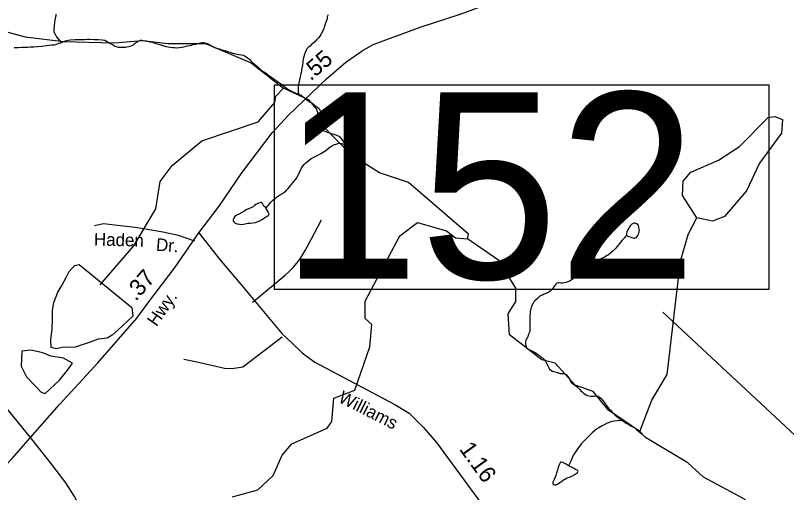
# Model space of a CAD drawing. Extents: x 2126262 to 2293712, y 749403 to 919119.
# Drawn here: x 2226868 to 2232664, y 782434 to 786018 of the extents above; entities that cross this region are included whole.
import ezdxf

# ---------------------------------------------------------------- set-up
doc = ezdxf.new("R2010")
doc.units = 0
for name, color, linetype in [('Exist Hydrographic Creek Single Shore', 7, 'Continuous'), ('Exist Hydrographic Misc Water Feature', 7, 'Continuous'), ('Exist Hydrographic Pond Over 1500 Sq Ft', 7, 'Continuous'), ('Exist Hydrographic Pond Under 1500 Sq Ft', 7, 'Continuous'), ('Exist Hydrographic Stream', 7, 'Continuous'), ('Exist Road Non-System Type 51', 7, 'Continuous'), ('Exist Road Non-System Type 51 Label', 7, 'Continuous'), ('Exist Road Secondary Mileage Hundredths English Label', 7, 'Continuous'), ('Exist Road Secondary Structure Standard Bridge Number Label', 7, 'Continuous'), ('Exist Road Secondary Type 51 Attributed', 7, 'Continuous'), ('Exist Road Secondary Type 51 Label', 7, 'Continuous')]:
    doc.layers.add(name, color=color, linetype=linetype)

msp = doc.modelspace()

# ---------------------------------------------------------------- linework, layer by layer
at = {"layer": 'Exist Hydrographic Creek Single Shore'}
for points in [[(2226705.1, 785919), (2226942.7, 785856.7), (2227230.2, 785821.6), (2227614.1, 785811.8), (2227822.2, 785830.4), (2228013.1, 785806.7), (2228297.1, 785807.5), (2228639.2, 785662.6), (2228883.2, 785470.7)], [(2230266.3, 784340.1), (2230274.3, 784375.9), (2229821.3, 784762.5), (2229604.1, 784835.9), (2229395.2, 784968.1), (2229160.2, 785205.8), (2229134.2, 785314.6), (2229075.1, 785381.5), (2228883.2, 785470.7)], [(2231561.2, 782893), (2231326.2, 783052.1), (2231209.3, 783192.2), (2231075.2, 783240.9), (2230924.3, 783404.8), (2230823.2, 783429.8), (2230580.2, 783618.5), (2230571.2, 783776.1), (2230628.2, 783870.1), (2230628.2, 783968.5), (2230501.3, 784177.8), (2230266.3, 784340.1)], [(2233735.1, 781992.2), (2233626.3, 782037.1), (2233349.7, 782118.2), (2233278.9, 782118.2), (2233213.7, 782138.7), (2233083.3, 782187.2), (2232927.7, 782184.1), (2232856, 782207.7), (2232796.4, 782211.4), (2232574.1, 782235.9), (2232499.3, 782244), (2232348.2, 782384.8), (2232038.1, 782548.7), (2231921.2, 782656.1), (2231603.2, 782846.3), (2231561.2, 782893)]]:
    msp.add_lwpolyline(points, dxfattribs=at)
at = {"layer": 'Exist Hydrographic Misc Water Feature'}
msp.add_line((2228976.8, 785433.8), (2228995.1, 785428.2), dxfattribs=at)
for points in [[(2229218.2, 786023.7), (2229212, 786007.5), (2229210.4, 785991.6), (2229196.9, 785951.5), (2229188.9, 785929.5), (2229184.8, 785919.2), (2229173.1, 785893.4), (2229163.4, 785875.4), (2229155.4, 785863.2), (2229145.8, 785848.8), (2229133.5, 785836.8), (2229119.8, 785822.7), (2229105.8, 785810.6), (2229089.8, 785796.4), (2229082.2, 785788.6), (2229068.3, 785776.6), (2229058, 785766.3), (2229054.4, 785756.4), (2229046.6, 785740.5), (2229038.6, 785720.2), (2229034.9, 785708.2), (2229031, 785690.1), (2229028.9, 785678.2), (2229027.1, 785662.2), (2229024.8, 785646), (2229021.3, 785622.1), (2229019.3, 785610.3), (2229017.6, 785598), (2229013.3, 785582), (2229009.9, 785565.9), (2229007.8, 785558.1), (2229002.1, 785533.8), (2228998.4, 785512), (2228996.5, 785498.1), (2228994.3, 785479.8), (2228992.6, 785457.7), (2228992.8, 785446), (2228995.1, 785428.2)], [(2227214.8, 785815.4), (2227230.2, 785821.6), (2227244.4, 785827.5), (2227264.2, 785831.8), (2227282.3, 785836), (2227316.3, 785838.2), (2227334.6, 785838.3), (2227352, 785838.5), (2227368.6, 785838.4), (2227388.3, 785838.7), (2227406.6, 785838.8), (2227428.3, 785839.1), (2227460.3, 785837.1), (2227492.1, 785837.6), (2227520.4, 785835.8), (2227540, 785832), (2227552.3, 785826.1), (2227562.4, 785820.1), (2227570.2, 785814), (2227580.2, 785808.1), (2227592.5, 785802.2), (2227602.6, 785796.6), (2227616.5, 785788.4), (2227632.5, 785782.7), (2227642.6, 785780.8), (2227658.8, 785778.8), (2227668.4, 785778.9), (2227684.6, 785778.9), (2227694.4, 785779.1), (2227706.5, 785783.3), (2227720.5, 785785.3), (2227730.7, 785787.4), (2227742.4, 785791.7), (2227752.3, 785797.5), (2227760.3, 785801.6), (2227770.5, 785811.8), (2227778.3, 785817.9), (2227791.8, 785826), (2227808.2, 785832.1), (2227818.1, 785832.2), (2227839.8, 785828.5), (2227854, 785826.4), (2227861.8, 785824.4), (2227879.8, 785820.8), (2227898.3, 785816.8), (2227916.5, 785810.8), (2227932.5, 785805.2), (2227952.4, 785799.4), (2227974.3, 785793.6), (2228000.2, 785785.6), (2228016.6, 785781.9), (2228032.4, 785780), (2228050.8, 785778), (2228066.6, 785776.4), (2228080.4, 785774.3), (2228102.5, 785776.7), (2228118.5, 785778.8), (2228134.5, 785782.8), (2228152.1, 785787.1), (2228164.2, 785790.9), (2228192.1, 785795.2), (2228200.5, 785799.2), (2228226.4, 785803.5), (2228238, 785807.8), (2228248.1, 785809.9), (2228260, 785811.8), (2228272.1, 785816), (2228281.9, 785814.1), (2228292, 785812.2), (2228302.2, 785810.2), (2228316.2, 785804.5), (2228322.3, 785800.3), (2228334.4, 785794.4), (2228342.2, 785790.4), (2228364.6, 785778.5), (2228380.5, 785772.9), (2228400.4, 785767), (2228418.5, 785761), (2228430.6, 785757.2), (2228448.8, 785751.2), (2228470.8, 785745.4), (2228482.9, 785741.6), (2228500.5, 785735.6), (2228514.9, 785731.9), (2228532.5, 785728), (2228548.9, 785724.3), (2228566.7, 785722.4), (2228581.1, 785718.7), (2228590.5, 785714.4), (2228609, 785702.7), (2228627, 785689), (2228635, 785680.9), (2228644.9, 785670.9), (2228651.2, 785665.1), (2228677.3, 785641.2), (2228701.7, 785619.3), (2228717.7, 785605.5), (2228735.7, 785593.9), (2228751.9, 785583.7), (2228764, 785572.2)], [(2226858.9, 785776.2), (2226871, 785776.4), (2226888.8, 785776.6), (2226916.7, 785778.8), (2226940.9, 785780.9), (2226958.7, 785781), (2226980.9, 785783.4), (2227006.7, 785783.5), (2227034.8, 785785.8), (2227064.9, 785788.1), (2227100.8, 785792.4), (2227120.9, 785794.6), (2227140.6, 785796.5), (2227156.8, 785798.6), (2227172.4, 785801.1), (2227194.5, 785809.1), (2227206.6, 785812.9), (2227214.8, 785815.4)], [(2228764, 785572.2), (2228792.1, 785554.1), (2228812, 785538.5), (2228834.3, 785524.6), (2228846.2, 785516.8), (2228868.2, 785500.9), (2228888.5, 785485.2), (2228902.6, 785475.4), (2228916.6, 785465.1), (2228932.8, 785455.4), (2228952.9, 785445.5), (2228970.7, 785437.9), (2228976.8, 785433.8)], [(2227504.2, 783993.4), (2227759.1, 784286.7), (2227924.1, 784565.4), (2227955.1, 784771.4), (2228046.1, 784890.9), (2228269.3, 785076.5), (2228693.1, 785218.7), (2228817.2, 785363.8), (2228825.2, 785412.8), (2228883.2, 785470.7)], [(2228995.1, 785428.2), (2229003.3, 785424.1), (2229017.2, 785416.3), (2229026.9, 785410.4), (2229037.1, 785402.3), (2229051.3, 785390.5), (2229065.4, 785378.6), (2229079.4, 785368.8), (2229093.5, 785361), (2229105.8, 785353), (2229115.9, 785345), (2229129.6, 785335.2), (2229137.8, 785329.1), (2229149.9, 785319.2), (2229155.9, 785307.3), (2229162, 785295.4), (2229164.1, 785279.3), (2229163.8, 785271.2), (2229164.3, 785257.4), (2229164.1, 785241.6), (2229164.7, 785229.3), (2229164.9, 785215.5), (2229164.7, 785199.3), (2229164.7, 785191.6), (2229166.7, 785177.5), (2229170.8, 785167.5), (2229175.1, 785161.7), (2229181.3, 785155.4), (2229184.8, 785151.7), (2229194.8, 785147.7), (2229205.3, 785143.7), (2229215.1, 785139.8), (2229229.5, 785136), (2229235.4, 785134.3), (2229245.5, 785129.9), (2229257.6, 785126.1), (2229265.3, 785124.5), (2229277.4, 785120.2), (2229291.2, 785114.5), (2229301.2, 785110.5), (2229307.4, 785104.7), (2229313.3, 785097), (2229319.3, 785088.8), (2229325.6, 785078.9), (2229335.7, 785064.8), (2229348, 785049.1)], [(2228750.3, 784570.2), (2228754.4, 784576.5), (2228766, 784588.5), (2228771.6, 784596.6), (2228785.7, 784612.7), (2228793.5, 784620.9), (2228803.6, 784630.7), (2228819.4, 784642.9), (2228831, 784652.9), (2228845.6, 784662.9), (2228860.8, 784673.2), (2228879.2, 784683.4), (2228889.1, 784689.6), (2228899.3, 784697.4), (2228906.7, 784705.6), (2228916.8, 784717.5), (2228926.8, 784729.8), (2228940.5, 784745.9), (2228952.2, 784760), (2228960.2, 784769.7), (2228976, 784788), (2228985.9, 784804), (2228993.9, 784818.2), (2229001.9, 784836.1), (2229009.6, 784854.4), (2229019.3, 784874.4), (2229029.3, 784886.3), (2229039.4, 784898.5), (2229049.2, 784908.4), (2229061.1, 784918.8), (2229091.1, 784943.1), (2229110.5, 784953.1), (2229134.7, 784965.3), (2229146.8, 784971.6), (2229164.7, 784981.5), (2229176.6, 784989.8), (2229188.2, 784995.8), (2229200.1, 785003.7), (2229221.9, 785021.9), (2229237.9, 785034.1), (2229252, 785042.1), (2229265.8, 785048.6), (2229277.9, 785052.4), (2229291.8, 785056.4), (2229304.1, 785058.6), (2229311.7, 785058.7), (2229321.5, 785056.8), (2229333.8, 785050.9), (2229348, 785049.1)], [(2228750.3, 784570.2), (2228748, 784574.2), (2228735.9, 784586.2), (2228730, 784596), (2228724, 784606.2), (2228716, 784611.9), (2228708, 784609.9), (2228695.7, 784608), (2228685.7, 784603.9), (2228675.8, 784597.7), (2228663.9, 784589.7), (2228653.9, 784581.5), (2228638.1, 784573.3), (2228626.2, 784567.4), (2228608.2, 784559.2), (2228588.3, 784546.8), (2228570, 784537), (2228546.8, 784524.7), (2228530.4, 784516.6), (2228516.5, 784506.5), (2228508.5, 784494.3), (2228504.6, 784486.4), (2228504.8, 784476.2), (2228508.9, 784468.3), (2228518.8, 784458.7), (2228535.2, 784452.6), (2228551.2, 784448.9), (2228571, 784448.7), (2228595.2, 784453.2), (2228614.9, 784457.1), (2228632.8, 784457.3), (2228653.3, 784459.5), (2228673, 784463.8), (2228688.9, 784469.9), (2228704.7, 784476.1), (2228722.8, 784484.3), (2228736.3, 784494.4), (2228748.6, 784502.3), (2228758.7, 784508.5), (2228768.5, 784516.3), (2228772.6, 784520.6), (2228774.2, 784528.5), (2228770.4, 784538.3), (2228762.4, 784550.5), (2228750.3, 784570.2)], [(2228499.1, 782401.8), (2228691.2, 782453.5), (2228806.1, 782562.7), (2228872.1, 782715.6), (2228946.1, 782799.3), (2229212.1, 782918.5), (2229245.1, 782967), (2229260.3, 783143.9), (2229418.1, 783202.9), (2229532.2, 783528.5), (2229547.1, 783695.6), (2229496.1, 783742.5), (2229496.1, 783870.4), (2229758.1, 784363.6), (2229890.2, 784462.6), (2230108.2, 784399.1), (2230175.2, 784348.5), (2230266.3, 784340.1)], [(2231462.3, 784366.5), (2231466.8, 784362.6), (2231474.6, 784356.5), (2231488.9, 784354.8), (2231501, 784350.9), (2231510.9, 784347), (2231517, 784345.2), (2231523, 784345.1), (2231526.7, 784347), (2231534.9, 784351), (2231540.6, 784357.1), (2231546.6, 784365.1), (2231550.4, 784375.5), (2231554.3, 784385.4), (2231556.4, 784393.2), (2231558.2, 784403.5), (2231556.4, 784413.1), (2231554.1, 784423.2), (2231552.1, 784431.2), (2231550, 784439.2), (2231545.9, 784447.1), (2231539.8, 784451.4), (2231535.9, 784453.1), (2231529.7, 784455.2), (2231523.8, 784457), (2231515.6, 784457), (2231509.8, 784455), (2231505.5, 784452.8), (2231501.9, 784450.9), (2231498.2, 784446.6), (2231494.1, 784442.8), (2231488.1, 784436.8), (2231484.2, 784428.9), (2231478.3, 784418.9), (2231470.3, 784406.6), (2231466.4, 784398.7), (2231462.1, 784390.5), (2231460.8, 784380.5), (2231460.6, 784376.5), (2231460.4, 784370.4), (2231462.3, 784366.5)], [(2231561.2, 782893), (2231651.2, 783127.4), (2231766.2, 783321.8), (2231867.3, 784172.6), (2231924.3, 784371.5), (2231989.3, 784498.1)], [(2231462.3, 784366.5), (2231451, 784354.4), (2231444.8, 784348.4), (2231434.6, 784338.2), (2231427, 784330.4), (2231417.4, 784318.1), (2231406.9, 784304.2), (2231399.3, 784294), (2231389.3, 784282.2), (2231379.4, 784269.8), (2231371.4, 784260.1), (2231359.5, 784249.7), (2231343.8, 784235.9), (2231326.1, 784219.5), (2231316.1, 784215.3), (2231295.8, 784203.4), (2231274.2, 784191.2), (2231254.1, 784180.8), (2231230.4, 784170.6), (2231212.3, 784158.8), (2231192.6, 784148.3), (2231174.6, 784136.5), (2231156.7, 784124.1), (2231142.8, 784114.1), (2231126.6, 784103.9), (2231113.1, 784093.8), (2231102.8, 784085.6), (2231091.3, 784077.6), (2231087.2, 784073.4), (2231081.1, 784065.4), (2231073.1, 784055.7), (2231063.2, 784047.4), (2231057.7, 784041.3), (2231051.6, 784035.4), (2231043.8, 784029.3), (2231031.7, 784022.9), (2231019.6, 784017.1), (2231005.8, 784013.1), (2230993.5, 784008.8), (2230981.8, 784007), (2230967.7, 784006.6), (2230953.5, 784008.4), (2230947.6, 784008.5), (2230938, 784006.3), (2230929.8, 784000.2), (2230923.6, 783992.2), (2230920.1, 783986.2), (2230910.1, 783972.3), (2230900, 783960), (2230888.3, 783948.1), (2230874.4, 783936), (2230860, 783932), (2230842.6, 783923.7), (2230828.5, 783915.7), (2230820.5, 783913.7), (2230804.5, 783903.5), (2230790.9, 783891.4), (2230772.9, 783875), (2230765.1, 783866.9), (2230756.9, 783851.1), (2230747.3, 783833.1), (2230741.1, 783814.9), (2230737.4, 783794.8), (2230735.6, 783778.8), (2230733.7, 783764.9), (2230733.9, 783751), (2230734.1, 783734.8), (2230734.1, 783717), (2230734.3, 783702.7), (2230734.3, 783695), (2230734.8, 783678.8), (2230734.5, 783665), (2230734.5, 783652.8), (2230732.9, 783642.9), (2230728.8, 783633), (2230724.9, 783623), (2230721.2, 783612.6), (2230715.5, 783598.9), (2230707.5, 783586.7), (2230703.2, 783576.8), (2230701.5, 783566.5), (2230701.5, 783556.8), (2230701.7, 783546.6), (2230706, 783534.6), (2230707.9, 783522.6), (2230712, 783516.7)], [(2230712, 783516.7), (2230717.7, 783513), (2230740.3, 783503), (2230754.2, 783496.9), (2230774.3, 783485.4), (2230792.4, 783473.3), (2230806.3, 783463.5), (2230820.1, 783451.7), (2230828.1, 783445.6), (2230844.7, 783430.1), (2230852.7, 783420), (2230858.8, 783406), (2230871.1, 783380.3), (2230877.1, 783370.1), (2230883, 783360.2), (2230891, 783354.1), (2230903.3, 783346.6), (2230921.6, 783340.6), (2230939.6, 783336.7), (2230965.4, 783328.7), (2230981.2, 783329.2), (2230993.1, 783327.4), (2231001.5, 783323.3), (2231009.1, 783321.3), (2231015.3, 783311.5), (2231025.5, 783299.4), (2231031.7, 783287.5), (2231035.4, 783279.6), (2231041.9, 783267.7), (2231045.6, 783259.8), (2231052, 783253.6), (2231062, 783247.6), (2231078.2, 783237.9), (2231090.1, 783228), (2231102.2, 783216), (2231110.2, 783208.3), (2231118.4, 783198.1), (2231128, 783190.2), (2231138.3, 783180.5), (2231156.7, 783168.4), (2231168.4, 783162.5), (2231178.3, 783160.7), (2231192.4, 783158.9), (2231216.8, 783158.9), (2231228.7, 783159.2), (2231244.5, 783157.2), (2231256.6, 783151.3), (2231266.9, 783143.6), (2231280.8, 783127.7), (2231293.1, 783111.7), (2231305, 783093.7), (2231315.5, 783080), (2231327.1, 783064), (2231339.2, 783052), (2231351.8, 783038.3), (2231359.3, 783030.3), (2231375.7, 783016.4), (2231387.8, 783004.5), (2231397.9, 782996.5), (2231422.4, 782976.2), (2231428.2, 782976.9)], [(2231428.2, 782976.9), (2231422.4, 782976.2), (2231390.1, 782972.5), (2231368.2, 782970.6), (2231342.1, 782964.4), (2231324.5, 782958.1), (2231314.4, 782953.9), (2231298.2, 782945.8), (2231276.5, 782935.7), (2231252.5, 782919.5), (2231234.3, 782909.2), (2231218.7, 782895.4), (2231202.7, 782883.2), (2231181.2, 782858.8), (2231157.6, 782838.5), (2231137.3, 782816.4), (2231123.5, 782802.6), (2231109.8, 782784.4), (2231091.5, 782762), (2231084.2, 782750.1), (2231069.8, 782728), (2231062.2, 782716.1), (2231052.8, 782694.1), (2231044.6, 782675.8), (2231025.1, 782635.7)], [(2231428.2, 782976.9), (2231437.9, 782968.9), (2231449.8, 782961.1), (2231464.3, 782953.2), (2231478.3, 782945.4), (2231498.4, 782933.5), (2231512.3, 782925.7), (2231522.4, 782919.7), (2231536.5, 782907.8), (2231552.7, 782892), (2231565, 782882), (2231576.9, 782874.1)], [(2231025.1, 782635.7), (2231002.8, 782649.7), (2230982.7, 782659.2), (2230968.5, 782663.3), (2230964.8, 782661.1), (2230958.9, 782651), (2230953.1, 782637.3), (2230947, 782621.2), (2230943.3, 782601), (2230935.3, 782581.1), (2230929.8, 782562.9), (2230924, 782548.8), (2230915.8, 782533), (2230911.5, 782522.6), (2230908.2, 782512.6), (2230906, 782506.8), (2230907.8, 782502.9), (2230908, 782498.8), (2230912.1, 782495), (2230918.1, 782490.8), (2230926.3, 782490.8), (2230932, 782492.8), (2230938, 782495.2), (2230942.1, 782496.9), (2230950.1, 782501), (2230960.3, 782509.2), (2230970.4, 782515.4), (2230988, 782529.4), (2231001.5, 782537.4), (2231013.6, 782543.8), (2231031.7, 782550), (2231049.7, 782555.7), (2231067.6, 782566.1), (2231083.1, 782576.3), (2231091.3, 782584.4), (2231097.3, 782594.4), (2231095.4, 782598.3), (2231077, 782608), (2231063, 782615.8), (2231047, 782623.9), (2231035.2, 782629.8), (2231025.1, 782635.7)]]:
    msp.add_lwpolyline(points, dxfattribs=at)
at = {"layer": 'Exist Hydrographic Pond Over 1500 Sq Ft'}
for points in [[(2227347.9, 784148.3), (2227743.7, 783823.6), (2227751.9, 783758.1), (2227637.2, 783654.4), (2227596.3, 783616.2), (2227558.1, 783594.3), (2227489.9, 783586.1), (2227429.8, 783564.3), (2227369.8, 783542.5), (2227317.9, 783526.1), (2227219.7, 783523.4), (2227176, 783512.5), (2227137.8, 783523.4), (2227135.1, 783583.4), (2227143.3, 783659.8), (2227146, 783741.7), (2227146, 783801.7), (2227156.9, 783861.8), (2227186.9, 783938.2), (2227217, 783990.1), (2227255.2, 784058.3), (2227271.5, 784093.8), (2227293.4, 784118.3), (2227315.2, 784140.2)], [(2226915.4, 783496.1), (2226912.7, 783384.2), (2226950.9, 783302.3), (2227019.1, 783234.1), (2227062.8, 783187.7), (2227092.8, 783176.8), (2227199.2, 783277.8), (2227259.3, 783354.2), (2227297.5, 783406), (2227229.2, 783444.2), (2227133.7, 783457.9), (2227073.7, 783482.4), (2227019.1, 783496.1), (2226983.6, 783504.3)]]:
    msp.add_lwpolyline(points, close=True, dxfattribs=at)
at = {"layer": 'Exist Hydrographic Pond Under 1500 Sq Ft'}
msp.add_lwpolyline([(2231989.3, 784498.1), (2231880.2, 784664.4), (2231887.2, 784772.4), (2231945.2, 784840.1), (2232152.1, 784931), (2232310.2, 785032.7), (2232525.3, 785251.3), (2232574.4, 785260.1), (2232633.2, 785236), (2232625.2, 785134.4), (2232461.2, 784908.2), (2232362.3, 784700.3), (2232198.3, 784506.9), (2232106.2, 784472.7), (2231989.3, 784498.1)], dxfattribs=at)
at = {"layer": 'Exist Hydrographic Stream'}
msp.add_lwpolyline([(2227172.6, 786027), (2227170.9, 786016.7), (2227163.2, 785972.8), (2227161.3, 785961), (2227159.5, 785942.6), (2227155.8, 785914.8), (2227157.8, 785895), (2227165.8, 785876.7), (2227177.9, 785857), (2227186.1, 785845.2), (2227202.3, 785827), (2227214.8, 785815.4)], dxfattribs=at)
at = {"layer": 'Exist Road Non-System Type 51'}
for points in [[(2228216.7, 784323.4), (2228093.3, 784364.5), (2227976.2, 784389.8), (2227875.1, 784408.8), (2227767.2, 784424.7), (2227615.5, 784443.7), (2227530, 784453.2), (2227463.8, 784437.3)], [(2228649.6, 783864.7), (2228686.5, 783894.7), (2228894.2, 784066.9), (2228923.3, 784092.6), (2228954.5, 784124.1), (2228983.2, 784157.6), (2229007.2, 784189.6), (2229028.5, 784221.9), (2229045.7, 784252.2), (2229093.3, 784340.3), (2229169.6, 784482.4)], [(2228873.5, 783601.1), (2228576.6, 783376.4), (2228496.4, 783362.8), (2228440.4, 783366.5), (2228222.7, 783414.9), (2228135.1, 783434.3)]]:
    msp.add_lwpolyline(points, dxfattribs=at)
at = {"layer": 'Exist Road Secondary Structure Standard Bridge Number Label'}
msp.add_line((2233022.2, 782587.8), (2231734.3, 783788.8), dxfattribs=at)
msp.add_lwpolyline([(2228814.6, 785496.8), (2232530.5, 785496.8), (2232530.5, 783960.4), (2228814.6, 783960.4)], close=True, dxfattribs=at)
at = {"layer": 'Exist Road Secondary Type 51 Attributed'}
for points in [[(2228247.9, 784386), (2228400, 784585.7), (2228570.3, 784835.7), (2228797.1, 785135.3), (2228921.3, 785269.4), (2229206.7, 785542.5), (2229351.8, 785668.2), (2229473.3, 785753.4), (2229557, 785800.9), (2229916.4, 785932.9), (2230203.9, 786026.5), (2230458.1, 786117.8)], [(2226982.2, 782846.8), (2226763, 783114.4), (2226422, 783600.9), (2225847.2, 784338), (2225604.6, 784586.7), (2225534.8, 784711), (2225502.7, 784794.8), (2225440.6, 785140.5), (2225429.4, 785294.2), (2225420.7, 785817.8)], [(2226982.2, 782846.8), (2227199.6, 783094.3), (2227487.2, 783408.1), (2227781, 783742.7), (2227870.3, 783865.6), (2228067.8, 784126.1), (2228247.9, 784386)], [(2228247.9, 784386), (2228401.7, 784186.7), (2228583, 783973.7), (2228870.1, 783629.9), (2228947.4, 783554.9), (2229023.5, 783483.1), (2229117.7, 783412.8), (2229719.9, 783096.4), (2229826.7, 783030.1), (2229935.5, 782922.5), (2230031.8, 782809.4), (2230259.8, 782498.6), (2230501.8, 782172.3)], [(2222591.7, 779471.1), (2223238.7, 779707.8), (2223326.7, 779751.1), (2223532.5, 779891.4), (2223607.9, 779955.7), (2223831.9, 780130.3), (2224247.2, 780476.1), (2224970.8, 781060.7), (2225247.9, 781307.2), (2225811, 781830.3), (2226026, 782003.6), (2226551.4, 782410.7), (2226709.1, 782550.4), (2226842.4, 782686.6), (2226982.2, 782846.8)], [(2228927.6, 779796.6), (2228641.4, 780190.8), (2228440.4, 780452.7), (2228293.7, 780669.5), (2227955.3, 781133.8), (2227879.4, 781249.7), (2227805, 781382.8), (2227661.2, 781685.5), (2227490.2, 782056.1), (2227313.5, 782405.3), (2227246.9, 782507.6), (2227134.6, 782653.6), (2226982.2, 782846.8)]]:
    msp.add_lwpolyline(points, dxfattribs=at)

# ---------------------------------------------------------------- texts
at = {"layer": 'Exist Road Non-System Type 51 Label'}
for s, rotation, p in [('Haden', 358.60271, (2227457.7, 784290)), ('Dr.', 355.78464, (2227922.3, 784250.9))]:
    msp.add_text(s, height=95, rotation=rotation, dxfattribs=at).set_placement(p)
at = {"layer": 'Exist Road Secondary Mileage Hundredths English Label'}
for s, rotation, p in [('.55', 40.89676, (2229087.2, 785521.7)), ('.37', 48.71155, (2227773.5, 783865.5)), ('1.16', 305.86655, (2230199.5, 782760.1))]:
    msp.add_text(s, height=125, rotation=rotation, dxfattribs=at).set_placement(p)
at = {"layer": 'Exist Road Secondary Structure Standard Bridge Number Label'}
msp.add_text('152', height=1400, dxfattribs=at).set_placement((2228864.8, 784039.5))
at = {"layer": 'Exist Road Secondary Type 51 Label'}
for s, rotation, p in [('Hwy.', 55.16766, (2227928.5, 783675.1)), ('Williams', 333.12444, (2229288.2, 783118.2))]:
    msp.add_text(s, height=95, rotation=rotation, dxfattribs=at).set_placement(p)

doc.saveas('drawing.dxf')
